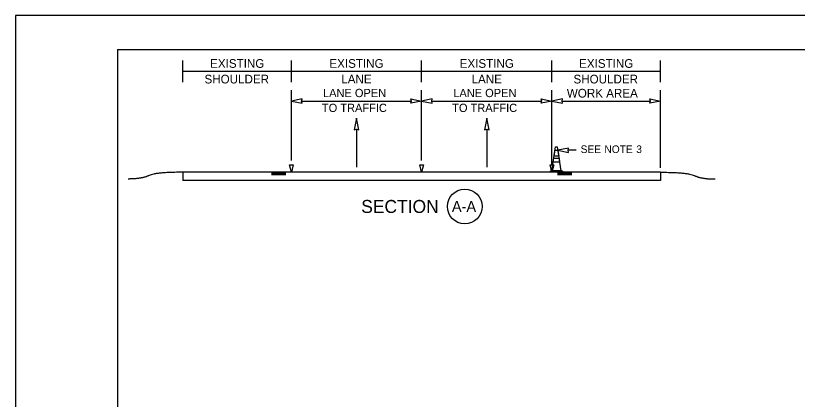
# Model space of a CAD drawing. Extents: x 99999.1 to 100055.7, y 99995 to 100010.7.
# Drawn here: x 99999.06 to 100006.26, y 100007.15 to 100010.69 of the extents above; entities that cross this region are included whole.
import ezdxf

# ---------------------------------------------------------------- set-up
doc = ezdxf.new("R2010")
doc.units = 0
for name, color, linetype in [('SH_GI_PlotLimits', 7, 'Continuous'), ('SH_GI_SheetBorder', 7, 'Continuous'), ('SH_TI_WZSectionCut', 7, 'Continuous'), ('TR_WZ_ArrowLeftStrRightTurn', 7, 'Continuous'), ('TR_WZ_TrafficConeElev', 7, 'Continuous'), ('TR_WZ_WorkZoneDetails', 7, 'Continuous'), ('TR_WZ_WorkZoneTextCurrent', 7, 'Continuous')]:
    doc.layers.add(name, color=color, linetype=linetype)

msp = doc.modelspace()

# ---------------------------------------------------------------- linework, layer by layer
at = {"layer": 'SH_GI_PlotLimits'}
msp.add_lwpolyline([(99999.0625, 99999.6875), (100016.0625, 99999.6875), (100016.0625, 100010.6875), (99999.0625, 100010.6875)], close=True, dxfattribs=at)
at = {"layer": 'SH_GI_SheetBorder'}
for q in [(100000, 100000), (100015.75, 100010.375)]:
    msp.add_line((100000, 100010.375), q, dxfattribs=at)
at = {"layer": 'SH_TI_WZSectionCut'}
for p, q in [((100000.6021, 100010.075), (100000.6021, 100010.275)), ((100001.6021, 100010.075), (100001.6021, 100010.275)), ((100002.8021, 100010.075), (100002.8021, 100010.275)), ((100004.0021, 100010.075), (100004.0021, 100010.275)), ((100005.0021, 100010.075), (100005.0021, 100010.275)), ((100000.6021, 100010.175), (100001.6021, 100010.175)), ((100001.6021, 100010.175), (100002.8021, 100010.175)), ((100002.8021, 100010.175), (100004.0021, 100010.175)), ((100004.0021, 100010.175), (100005.0021, 100010.175)), ((100001.6021, 100009.3547), (100001.6021, 100010.001)), ((100002.8021, 100009.3547), (100002.8021, 100010.001)), ((100004.0021, 100009.3147), (100004.0021, 100010.001)), ((100005.0021, 100009.2849), (100005.0021, 100010.001)), ((100001.6958, 100009.901), (100002.7084, 100009.901)), ((100002.8958, 100009.901), (100003.9084, 100009.901)), ((100004.0958, 100009.901), (100004.9084, 100009.901)), ((100000.6021, 100009.2449), (100000.6021, 100009.1699)), ((100005.0021, 100009.2449), (100000.6021, 100009.2449)), ((100001.4191, 100009.2397), (100001.5521, 100009.2397)), ((100001.4191, 100009.2341), (100001.5521, 100009.2341)), ((100001.4191, 100009.2284), (100001.5521, 100009.2284)), ((100001.4191, 100009.2232), (100001.5521, 100009.2232)), ((100004.1851, 100009.2393), (100004.0521, 100009.2393)), ((100004.1851, 100009.2337), (100004.0521, 100009.2337)), ((100004.1851, 100009.228), (100004.0521, 100009.228)), ((100004.1851, 100009.2228), (100004.0521, 100009.2228)), ((100005.0021, 100009.2449), (100005.0021, 100009.1699)), ((100005.0021, 100009.1699), (100000.6021, 100009.1699))]:
    msp.add_line(p, q, dxfattribs=at)
for points in [[(100001.6021, 100009.901), (100001.7004, 100009.8817), (100001.6958, 100009.901), (100001.7004, 100009.9203)], [(100002.8021, 100009.901), (100002.7038, 100009.8817), (100002.7084, 100009.901), (100002.7038, 100009.9203)], [(100002.8021, 100009.901), (100002.9004, 100009.8817), (100002.8958, 100009.901), (100002.9004, 100009.9203)], [(100004.0021, 100009.901), (100003.9038, 100009.8817), (100003.9084, 100009.901), (100003.9038, 100009.9203)], [(100004.0021, 100009.901), (100004.1004, 100009.8817), (100004.0958, 100009.901), (100004.1004, 100009.9203)], [(100005.0021, 100009.901), (100004.9038, 100009.8817), (100004.9084, 100009.901), (100004.9038, 100009.9203)], [(100001.5854, 100009.3147), (100001.6188, 100009.3147), (100001.6021, 100009.2449)], [(100002.7854, 100009.3147), (100002.8188, 100009.3147), (100002.8021, 100009.2449)], [(100003.9854, 100009.3147), (100004.0188, 100009.3147), (100004.0021, 100009.2449)]]:
    msp.add_lwpolyline(points, close=True, dxfattribs=at)
msp.add_circle((100003.1987, 100008.93), 0.16, dxfattribs=at)
for points in [[(100000.6021, 100009.2449), (100000.3509, 100009.2449), (100000.2255, 100009.1828), (100000.1, 100009.1828)], [(100005.0021, 100009.2449), (100005.2533, 100009.2451), (100005.3788, 100009.183), (100005.5043, 100009.1831)]]:
    msp.add_open_spline(points, degree=2, dxfattribs=at)
at = {"layer": 'TR_WZ_ArrowLeftStrRightTurn'}
for p, q in [((100002.2021, 100009.6418), (100002.2021, 100009.292)), ((100003.4021, 100009.6418), (100003.4021, 100009.292))]:
    msp.add_line(p, q, dxfattribs=at)
for points in [[(100002.2021, 100009.742), (100002.1815, 100009.6369), (100002.2021, 100009.6418), (100002.2227, 100009.6369)], [(100003.4021, 100009.742), (100003.3815, 100009.6369), (100003.4021, 100009.6418), (100003.4227, 100009.6369)]]:
    msp.add_lwpolyline(points, close=True, dxfattribs=at)
at = {"layer": 'TR_WZ_TrafficConeElev'}
for p, q in [((100004.0229, 100009.3929), (100004.0312, 100009.4471)), ((100004.0312, 100009.4471), (100004.0564, 100009.4471)), ((100004.0564, 100009.4471), (100004.0647, 100009.3929)), ((100004.0146, 100009.3388), (100004.0203, 100009.3763)), ((100004.073, 100009.3388), (100004.0146, 100009.3388)), ((100004.0203, 100009.3763), (100004.0672, 100009.3763)), ((100004.0647, 100009.3929), (100004.0229, 100009.3929)), ((100004.0672, 100009.3763), (100004.073, 100009.3388)), ((100003.986, 100009.2533), (100003.9901, 100009.2575)), ((100003.986, 100009.245), (100003.986, 100009.2533)), ((100004.1016, 100009.245), (100003.986, 100009.245)), ((100004.0854, 100009.2575), (100004.0974, 100009.2575)), ((100004.0974, 100009.2575), (100004.1016, 100009.2533)), ((100004.1016, 100009.2533), (100004.1016, 100009.245))]:
    msp.add_line(p, q, dxfattribs=at)
msp.add_lwpolyline([(100004.0854, 100009.2575), (100004.0021, 100009.2575), (100004.036, 100009.4783), (100004.0516, 100009.4783)], close=True, dxfattribs=at)
msp.add_lwpolyline([(100004.0854, 100009.2575), (100004.0021, 100009.2575), (100004.036, 100009.4783), (100004.0516, 100009.4783)], close=True, dxfattribs=at)
msp.add_lwpolyline([(100003.9901, 100009.2575), (100004.0021, 100009.2575), (100004.0854, 100009.2575)], dxfattribs=at)
at = {"layer": 'TR_WZ_WorkZoneDetails'}
msp.add_line((100004.2263, 100009.4471), (100004.1501, 100009.4471), dxfattribs=at)
msp.add_lwpolyline([(100004.0564, 100009.4471), (100004.1547, 100009.4279), (100004.1501, 100009.4472), (100004.1546, 100009.4664)], close=True, dxfattribs=at)

# ---------------------------------------------------------------- texts
at = {"layer": 'SH_TI_WZSectionCut'}
for s, height, p in [('EXISTING', 0.08, (100000.8538, 100010.207)), ('EXISTING', 0.08, (100001.9523, 100010.207)), ('EXISTING', 0.08, (100003.1523, 100010.207)), ('EXISTING', 0.08, (100004.2523, 100010.207)), ('SHOULDER', 0.08, (100000.8019, 100010.063)), ('LANE', 0.08, (100002.0617, 100010.063)), ('LANE', 0.08, (100003.2617, 100010.063)), ('SHOULDER', 0.08, (100004.2004, 100010.063)), ('SECTION', 0.12, (100002.2456, 100008.87)), ('A-A', 0.1, (100003.0808, 100008.88))]:
    msp.add_text(s, height=height, rotation=360, dxfattribs=at).set_placement(p)
for s, height, p in [('LANE OPEN', 0.076, (100001.8934, 100009.937)), ('LANE OPEN', 0.076, (100003.0934, 100009.937)), ('WORK AREA', 0.08, (100004.1392, 100009.933)), ('TO TRAFFIC', 0.076, (100001.8834, 100009.8002)), ('TO TRAFFIC', 0.076, (100003.0834, 100009.8002))]:
    msp.add_text(s, height=height, dxfattribs=at).set_placement(p)
at = {"layer": 'TR_WZ_WorkZoneTextCurrent'}
for s, p in [('SEE', (100004.2663, 100009.4221)), ('NOTE', (100004.4856, 100009.4221)), ('3', (100004.7788, 100009.4221))]:
    msp.add_text(s, height=0.07, dxfattribs=at).set_placement(p)

doc.saveas('drawing.dxf')
